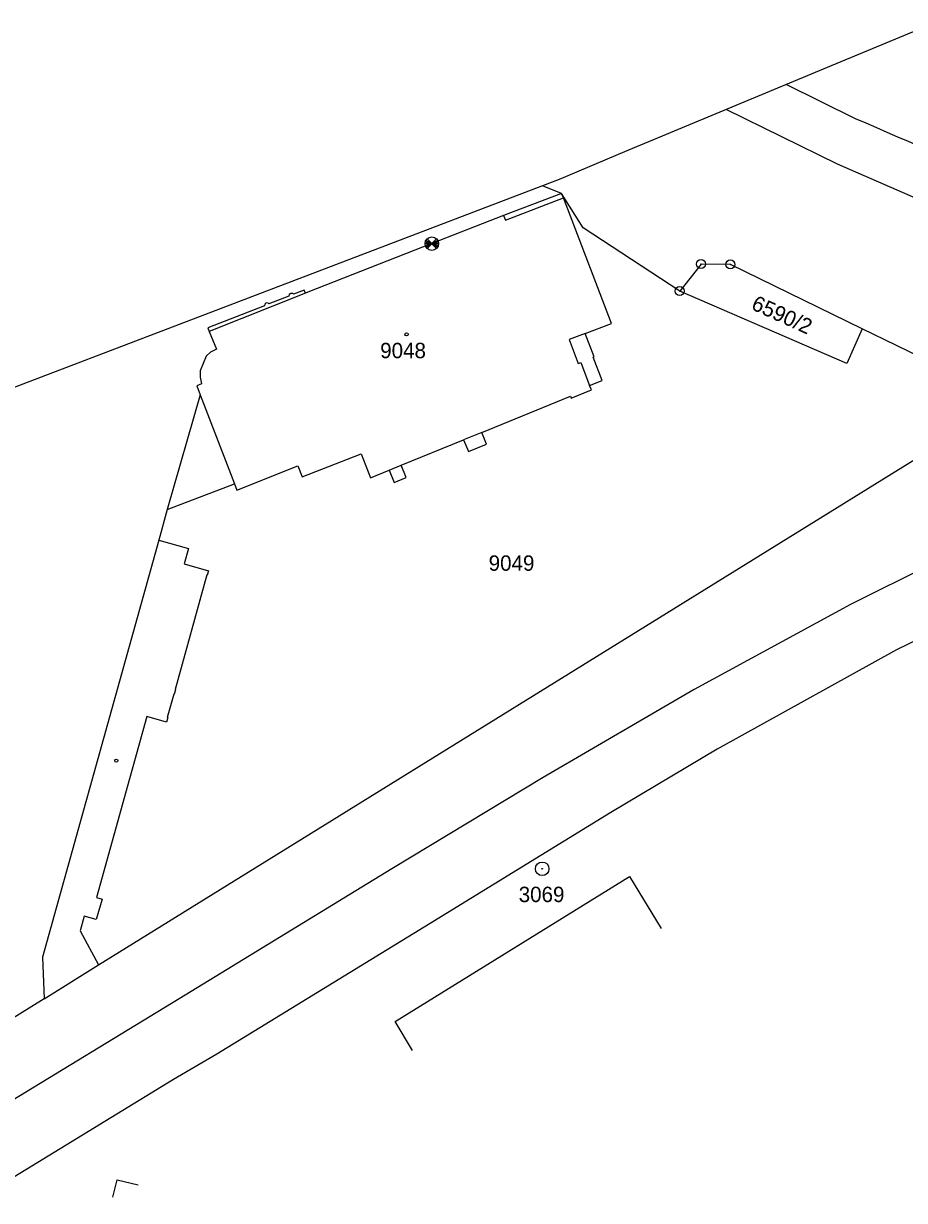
# Model space of a CAD drawing. Extents: x -825057 to -819383, y -1071633 to -1067888.
# Drawn here: x -824613.4 to -824516, y -1070018 to -1069888 of the extents above; entities that cross this region are included whole.
import ezdxf

# ---------------------------------------------------------------- set-up
doc = ezdxf.new("R2010")
doc.units = 0
for name, color, linetype in [('Vrstva 1', 7, 'Continuous'), ('Vrstva 10', 7, 'Continuous'), ('Vrstva 13', 7, 'Continuous'), ('Vrstva 17', 7, 'Continuous'), ('Vrstva 18', 7, 'Continuous'), ('Vrstva 19', 7, 'Continuous'), ('Vrstva 24', 7, 'Continuous'), ('Vrstva 25', 7, 'Continuous'), ('Vrstva 4', 7, 'Continuous')]:
    doc.layers.add(name, color=color, linetype=linetype)

msp = doc.modelspace()

# ---------------------------------------------------------------- linework, layer by layer
at = {"layer": 'Vrstva 1'}
for p, q in [((-824553.92, -1069906.73), (-824560.33, -1069909.17)), ((-824553.92, -1069906.73), (-824556.05, -1069905.9)), ((-824553.73, -1069907.23), (-824553.92, -1069906.73)), ((-824551.54, -1069910.52), (-824553.92, -1069906.73)), ((-824548.4, -1069921.1), (-824553.73, -1069907.23)), ((-824560.33, -1069909.17), (-824568.27, -1069912.28)), ((-824540.87, -1069917.52), (-824551.54, -1069910.52)), ((-824568.27, -1069912.28), (-824581.96, -1069917.65)), ((-824538.52, -1069914.54), (-824540.87, -1069917.52)), ((-824535.27, -1069914.58), (-824538.52, -1069914.54)), ((-824520.71, -1069921.68), (-824535.27, -1069914.58)), ((-824582.23, -1069917.76), (-824592.86, -1069921.99)), ((-824581.96, -1069917.65), (-824582.23, -1069917.76)), ((-824522.42, -1069925.54), (-824540.87, -1069917.52)), ((-824551.32, -1069922.21), (-824548.4, -1069921.1)), ((-824592.86, -1069921.99), (-824592.06, -1069923.96)), ((-824550.33, -1069924.78), (-824551.32, -1069922.21)), ((-824520.71, -1069921.68), (-824522.42, -1069925.54)), ((-824504.43, -1069929.62), (-824520.71, -1069921.68)), ((-824593.22, -1069924.7), (-824593.86, -1069926.32)), ((-824592.71, -1069924.28), (-824593.22, -1069924.7)), ((-824592.06, -1069923.96), (-824592.71, -1069924.28)), ((-824550.43, -1069924.82), (-824550.33, -1069924.78)), ((-824549.43, -1069927.41), (-824550.43, -1069924.82)), ((-824593.86, -1069926.32), (-824593.87, -1069927.02)), ((-824593.72, -1069927.78), (-824594.25, -1069927.98)), ((-824593.87, -1069927.02), (-824593.72, -1069927.78)), ((-824550.83, -1069927.95), (-824549.43, -1069927.41)), ((-824593.86, -1069929), (-824597.5, -1069941.67)), ((-824594.25, -1069927.98), (-824593.86, -1069929)), ((-824562.76, -1069933.14), (-824552.95, -1069929.14)), ((-824552.95, -1069929.14), (-824552.86, -1069929.35)), ((-824552.86, -1069929.35), (-824550.64, -1069928.45)), ((-824550.64, -1069928.45), (-824550.83, -1069927.95)), ((-824605.11, -1069991.98), (-824504.43, -1069929.62)), ((-824571.67, -1069936.77), (-824564.76, -1069933.95)), ((-824564.76, -1069933.95), (-824564.23, -1069935.25)), ((-824562.23, -1069934.44), (-824562.76, -1069933.14)), ((-824582.59, -1069938.05), (-824576.08, -1069935.5)), ((-824576.08, -1069935.5), (-824575.04, -1069938.15)), ((-824564.23, -1069935.25), (-824562.23, -1069934.44)), ((-824589.8, -1069939.53), (-824583.07, -1069936.85)), ((-824583.07, -1069936.85), (-824582.59, -1069938.05)), ((-824571.11, -1069938.14), (-824571.67, -1069936.77)), ((-824575.04, -1069938.15), (-824572.98, -1069937.3)), ((-824572.98, -1069937.3), (-824572.42, -1069938.67)), ((-824572.42, -1069938.67), (-824571.11, -1069938.14)), ((-824597.5, -1069941.67), (-824590.07, -1069938.84)), ((-824590.07, -1069938.84), (-824589.8, -1069939.53)), ((-824597.5, -1069941.67), (-824598.44, -1069945.05)), ((-824598.44, -1069945.05), (-824611.28, -1069991.13)), ((-824508.86, -1069953.22), (-824516.9, -1069957.15)), ((-824516.9, -1069957.15), (-824536.75, -1069968.14)), ((-824536.75, -1069968.14), (-824548.49, -1069975.13)), ((-824548.49, -1069975.13), (-824569.1, -1069987.81)), ((-824572.33, -1069998.25), (-824546.42, -1069982.22)), ((-824546.42, -1069982.22), (-824542.94, -1069987.97)), ((-824569.1, -1069987.81), (-824592.01, -1070001.83)), ((-824611.28, -1069991.13), (-824611.1, -1069995.72)), ((-824611.1, -1069995.72), (-824605.11, -1069991.98)), ((-824611.1, -1069995.72), (-824629.33, -1070007.06)), ((-824570.39, -1070001.43), (-824572.33, -1069998.25)), ((-824592.01, -1070001.83), (-824596.82, -1070004.64)), ((-824596.82, -1070004.64), (-824618.71, -1070018.01)), ((-824603.52, -1070017.66), (-824603.06, -1070015.73)), ((-824603.06, -1070015.73), (-824600.74, -1070016.29))]:
    msp.add_line(p, q, dxfattribs=at)
at = {"layer": 'Vrstva 10'}
for p, q in [((-824521.44, -1069898.48), (-824529.12, -1069894.71)), ((-824523.44, -1069903.5), (-824535.74, -1069897.46)), ((-824500.74, -1069913.38), (-824523.44, -1069903.5)), ((-824504.4, -1069943.41), (-824522.01, -1069952.14)), ((-824522.01, -1069952.14), (-824539.27, -1069961.56)), ((-824539.27, -1069961.56), (-824555.98, -1069971.29)), ((-824555.98, -1069971.29), (-824572.67, -1069981.37)), ((-824572.67, -1069981.37), (-824596.18, -1069995.72)), ((-824596.18, -1069995.72), (-824629.45, -1070015.96))]:
    msp.add_line(p, q, dxfattribs=at)
msp.add_spline([(-824462.57, -1069920.99), (-824483.8, -1069913.88), (-824521.44, -1069898.48)], degree=3, dxfattribs=at)
at = {"layer": 'Vrstva 13'}
for p, q in [((-824512.89, -1069887.96), (-824524.56, -1069892.82)), ((-824524.56, -1069892.82), (-824546.99, -1069902.13)), ((-824546.99, -1069902.13), (-824554.2, -1069905.19)), ((-824554.2, -1069905.19), (-824556.05, -1069905.9)), ((-824556.05, -1069905.9), (-824628.7, -1069933.6))]:
    msp.add_line(p, q, dxfattribs=at)
at = {"layer": 'Vrstva 24'}
for p, q in [((-824568.994, -1069912.086), (-824567.546, -1069912.474)), ((-824568.994, -1069912.474), (-824567.546, -1069912.086)), ((-824568.919, -1069911.905), (-824567.621, -1069912.655)), ((-824568.919, -1069912.655), (-824567.621, -1069911.905)), ((-824568.8, -1069912.81), (-824567.74, -1069911.75)), ((-824568.8, -1069911.75), (-824567.74, -1069912.81)), ((-824569.02, -1069912.28), (-824567.52, -1069912.28))]:
    msp.add_line(p, q, dxfattribs=at)
for centre, radius in [((-824568.27, -1069912.28), 0.75), ((-824538.52, -1069914.54), 0.5), ((-824538.52, -1069914.54), 0.0327), ((-824535.27, -1069914.58), 0.5), ((-824535.27, -1069914.58), 0.0327), ((-824540.87, -1069917.52), 0.5), ((-824540.87, -1069917.52), 0.0327), ((-824556.07, -1069981.36), 0.75), ((-824556.07, -1069981.36), 0.0327)]:
    msp.add_circle(centre, radius, dxfattribs=at)
at = {"layer": 'Vrstva 25'}
for centre in [(-824571.06, -1069922.31), (-824603.14, -1069969.41)]:
    msp.add_circle(centre, 0.175, dxfattribs=at)
at = {"layer": 'Vrstva 4'}
for p, q in [((-824560.14, -1069909.67), (-824553.73, -1069907.23)), ((-824560.33, -1069909.17), (-824560.14, -1069909.67)), ((-824582.37, -1069917.41), (-824583.54, -1069917.87)), ((-824582.23, -1069917.76), (-824582.37, -1069917.41)), ((-824584.08, -1069918.08), (-824586.27, -1069918.95)), ((-824584.03, -1069917.9), (-824584.08, -1069918.08)), ((-824583.86, -1069917.78), (-824584.03, -1069917.9)), ((-824583.65, -1069917.79), (-824583.86, -1069917.78)), ((-824583.54, -1069917.87), (-824583.65, -1069917.79)), ((-824586.75, -1069919.14), (-824593.02, -1069921.6)), ((-824586.73, -1069918.97), (-824586.75, -1069919.14)), ((-824586.57, -1069918.83), (-824586.73, -1069918.97)), ((-824586.37, -1069918.85), (-824586.57, -1069918.83)), ((-824586.27, -1069918.95), (-824586.37, -1069918.85)), ((-824593.02, -1069921.6), (-824592.86, -1069921.99)), ((-824551.32, -1069922.21), (-824553.09, -1069922.89)), ((-824553.09, -1069922.89), (-824552.09, -1069925.51)), ((-824552.09, -1069925.51), (-824551.81, -1069925.4)), ((-824551.81, -1069925.4), (-824550.83, -1069927.95)), ((-824593.86, -1069929), (-824590.07, -1069938.84)), ((-824562.76, -1069933.14), (-824564.76, -1069933.95)), ((-824572.98, -1069937.3), (-824571.67, -1069936.77)), ((-824598.44, -1069945.05), (-824595.15, -1069945.98)), ((-824595.15, -1069945.98), (-824595.62, -1069947.68)), ((-824595.62, -1069947.68), (-824592.95, -1069948.42)), ((-824592.95, -1069948.42), (-824593.08, -1069948.9)), ((-824593.14, -1069948.89), (-824596.65, -1069961.55)), ((-824593.08, -1069948.9), (-824593.14, -1069948.89)), ((-824596.59, -1069961.57), (-824596.73, -1069962.08)), ((-824596.65, -1069961.55), (-824596.59, -1069961.57)), ((-824596.79, -1069962.07), (-824597.5, -1069964.64)), ((-824596.73, -1069962.08), (-824596.79, -1069962.07)), ((-824599.77, -1069964.54), (-824605.34, -1069984.54)), ((-824597.58, -1069965.15), (-824599.77, -1069964.54)), ((-824597.44, -1069964.66), (-824597.58, -1069965.15)), ((-824597.5, -1069964.64), (-824597.44, -1069964.66)), ((-824604.7, -1069984.72), (-824605.36, -1069986.97)), ((-824605.34, -1069984.54), (-824604.7, -1069984.72)), ((-824606.68, -1069986.6), (-824607.13, -1069988.21)), ((-824605.36, -1069986.97), (-824606.68, -1069986.6)), ((-824607.13, -1069988.21), (-824605.11, -1069991.98))]:
    msp.add_line(p, q, dxfattribs=at)

# ---------------------------------------------------------------- texts
at = {"layer": 'Vrstva 17'}
msp.add_text('3069', height=1.7, dxfattribs=at).set_placement((-824558.668, -1069985.04))
at = {"layer": 'Vrstva 18'}
msp.add_text('6590/2', height=1.7, rotation=335.7, dxfattribs=at).set_placement((-824533.073, -1069919.49))
msp.add_text('9049', height=1.7, dxfattribs=at).set_placement((-824561.986, -1069948.43))
at = {"layer": 'Vrstva 19'}
msp.add_text('9048', height=1.7, dxfattribs=at).set_placement((-824573.974, -1069924.94))

doc.saveas('drawing.dxf')
